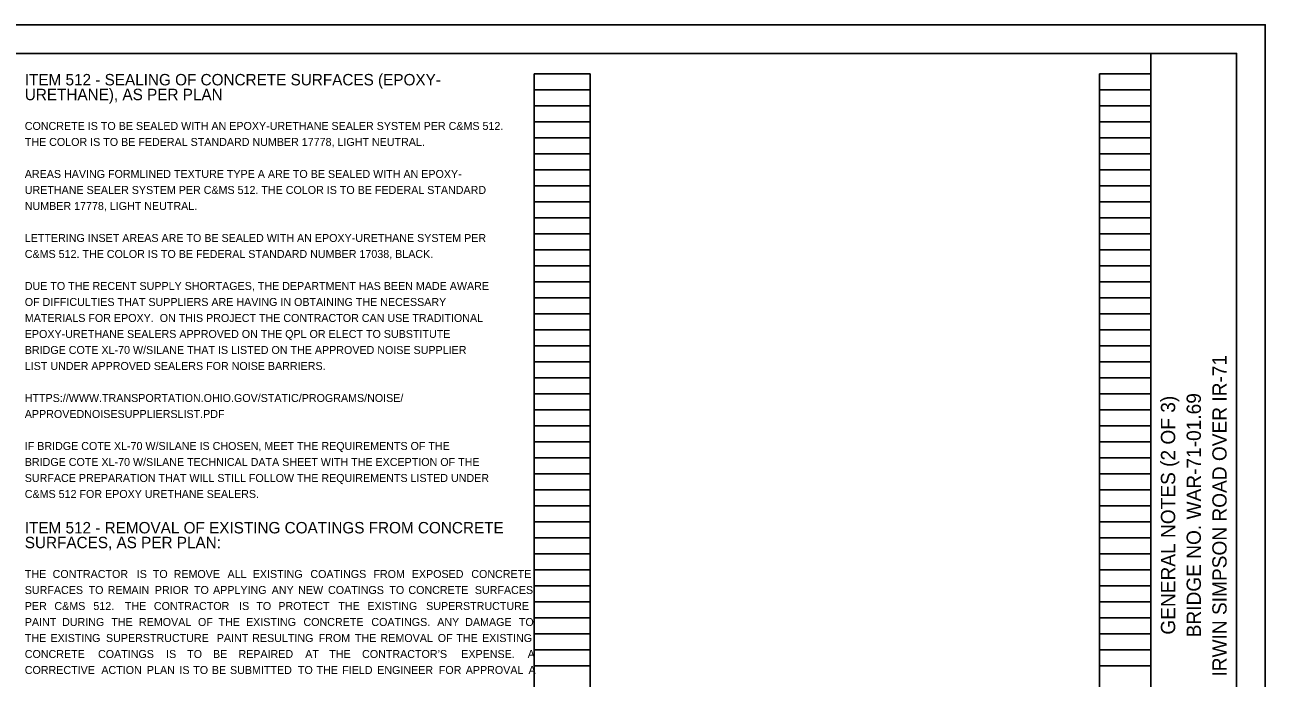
# Model space of a CAD drawing. Extents: x -20.1 to 34, y 0 to 22.
# Drawn here: x 12.29 to 34, y 10.57 to 22 of the extents above; entities that cross this region are included whole.
import ezdxf

# ---------------------------------------------------------------- set-up
doc = ezdxf.new("R2010")
doc.units = 0
for name, color, linetype in [('BR_P_Gen_Text', 7, 'Continuous'), ('SC_Scratch1', 7, 'Continuous'), ('SH_Border', 7, 'Continuous'), ('SH_Cut_Line', 7, 'Continuous'), ('SH_Data', 7, 'Continuous'), ('SH_Text', 7, 'Continuous')]:
    doc.layers.add(name, color=color, linetype=linetype)

msp = doc.modelspace()

# ---------------------------------------------------------------- linework, layer by layer
at = {"layer": 'SC_Scratch1'}
for p, q in [((21.207, 0.98), (21.207, 21.14)), ((21.207, 21.14), (22.187, 21.14)), ((22.187, 0.98), (22.187, 21.14)), ((31.1, 0.98), (31.1, 21.14)), ((31.1, 21.14), (32, 21.14)), ((32, 0.98), (32, 21.14)), ((21.207, 20.86), (22.187, 20.86)), ((31.1, 20.86), (32, 20.86)), ((21.207, 20.58), (22.187, 20.58)), ((31.1, 20.58), (32, 20.58)), ((21.207, 20.3), (22.187, 20.3)), ((31.1, 20.3), (32, 20.3)), ((21.207, 20.02), (22.187, 20.02)), ((31.1, 20.02), (32, 20.02)), ((21.207, 19.74), (22.187, 19.74)), ((31.1, 19.74), (32, 19.74)), ((21.207, 19.46), (22.187, 19.46)), ((31.1, 19.46), (32, 19.46)), ((21.207, 19.18), (22.187, 19.18)), ((31.1, 19.18), (32, 19.18)), ((21.207, 18.9), (22.187, 18.9)), ((31.1, 18.9), (32, 18.9)), ((21.207, 18.62), (22.187, 18.62)), ((31.1, 18.62), (32, 18.62)), ((21.207, 18.34), (22.187, 18.34)), ((31.1, 18.34), (32, 18.34)), ((21.207, 18.06), (22.187, 18.06)), ((31.1, 18.06), (32, 18.06)), ((21.207, 17.78), (22.187, 17.78)), ((31.1, 17.78), (32, 17.78)), ((21.207, 17.5), (22.187, 17.5)), ((31.1, 17.5), (32, 17.5)), ((21.207, 17.22), (22.187, 17.22)), ((31.1, 17.22), (32, 17.22)), ((21.207, 16.94), (22.187, 16.94)), ((31.1, 16.94), (32, 16.94)), ((21.207, 16.66), (22.187, 16.66)), ((31.1, 16.66), (32, 16.66)), ((21.207, 16.38), (22.187, 16.38)), ((31.1, 16.38), (32, 16.38)), ((21.207, 16.1), (22.187, 16.1)), ((31.1, 16.1), (32, 16.1)), ((21.207, 15.82), (22.187, 15.82)), ((31.1, 15.82), (32, 15.82)), ((21.207, 15.54), (22.187, 15.54)), ((31.1, 15.54), (32, 15.54)), ((21.207, 15.26), (22.187, 15.26)), ((31.1, 15.26), (32, 15.26)), ((21.207, 14.98), (22.187, 14.98)), ((31.1, 14.98), (32, 14.98)), ((21.207, 14.7), (22.187, 14.7)), ((31.1, 14.7), (32, 14.7)), ((21.207, 14.42), (22.187, 14.42)), ((31.1, 14.42), (32, 14.42)), ((21.207, 14.14), (22.187, 14.14)), ((31.1, 14.14), (32, 14.14)), ((21.207, 13.86), (22.187, 13.86)), ((31.1, 13.86), (32, 13.86)), ((21.207, 13.58), (22.187, 13.58)), ((31.1, 13.58), (32, 13.58)), ((21.207, 13.3), (22.187, 13.3)), ((31.1, 13.3), (32, 13.3)), ((21.207, 13.02), (22.187, 13.02)), ((31.1, 13.02), (32, 13.02)), ((21.207, 12.74), (22.187, 12.74)), ((31.1, 12.74), (32, 12.74)), ((21.207, 12.46), (22.187, 12.46)), ((31.1, 12.46), (32, 12.46)), ((21.207, 12.18), (22.187, 12.18)), ((31.1, 12.18), (32, 12.18)), ((21.207, 11.9), (22.187, 11.9)), ((31.1, 11.9), (32, 11.9)), ((21.207, 11.62), (22.187, 11.62)), ((31.1, 11.62), (32, 11.62)), ((21.207, 11.34), (22.187, 11.34)), ((31.1, 11.34), (32, 11.34)), ((21.207, 11.06), (22.187, 11.06)), ((31.1, 11.06), (32, 11.06)), ((21.207, 10.78), (22.187, 10.78)), ((31.1, 10.78), (32, 10.78))]:
    msp.add_line(p, q, dxfattribs=at)
msp.add_lwpolyline([(0, 22), (34, 22), (34, 0), (0, 0)], close=True, dxfattribs=at)
at = {"layer": 'SH_Border'}
msp.add_line((32, 0.5), (32, 21.5), dxfattribs=at)
msp.add_lwpolyline([(1.5, 21.5), (33.5, 21.5), (33.5, 0.5), (1.5, 0.5)], close=True, dxfattribs=at)
at = {"layer": 'SH_Cut_Line'}
msp.add_lwpolyline([(0, 0), (34, 0), (34, 22), (0, 22)], close=True, dxfattribs=at)

# ---------------------------------------------------------------- texts
at = {"layer": 'BR_P_Gen_Text'}
for s, p in [('ITEM 512 - SEALING OF CONCRETE SURFACES (EPOXY-', (12.293, 20.94)), ('URETHANE), AS PER PLAN', (12.293, 20.681)), ('ITEM 512 - REMOVAL OF EXISTING COATINGS FROM CONCRETE ', (12.293, 13.1)), ('SURFACES, AS PER PLAN:', (12.293, 12.841))]:
    msp.add_text(s, height=0.2, dxfattribs=at).set_placement(p)
at = {"layer": 'SH_Data'}
for s, p in [('IRWIN SIMPSON ROAD OVER IR-71', (33.325, 10.595)), ('GENERAL NOTES (2 OF 3)', (32.425, 11.329)), ('BRIDGE NO. WAR-71-01.69', (32.875, 11.282))]:
    msp.add_text(s, height=0.25, rotation=90, dxfattribs=at).set_placement(p)
at = {"layer": 'SH_Text'}
for s, p in [('CONCRETE IS TO BE SEALED WITH AN EPOXY-URETHANE SEALER SYSTEM PER C&MS 512. ', (12.293, 20.16)), ('THE COLOR IS TO BE FEDERAL STANDARD NUMBER 17778, LIGHT NEUTRAL. ', (12.293, 19.88)), ('AREAS HAVING FORMLINED TEXTURE TYPE A ARE TO BE SEALED WITH AN EPOXY-', (12.293, 19.32)), ('URETHANE SEALER SYSTEM PER C&MS 512. THE COLOR IS TO BE FEDERAL STANDARD ', (12.293, 19.04)), ('NUMBER 17778, LIGHT NEUTRAL. ', (12.293, 18.76)), ('LETTERING INSET AREAS ARE TO BE SEALED WITH AN EPOXY-URETHANE SYSTEM PER ', (12.293, 18.2)), ('C&MS 512. THE COLOR IS TO BE FEDERAL STANDARD NUMBER 17038, BLACK.', (12.293, 17.92)), ('DUE TO THE RECENT SUPPLY SHORTAGES, THE DEPARTMENT HAS BEEN MADE AWARE ', (12.293, 17.36)), ('OF DIFFICULTIES THAT SUPPLIERS ARE HAVING IN OBTAINING THE NECESSARY ', (12.293, 17.08)), ('MATERIALS FOR EPOXY.  ON THIS PROJECT THE CONTRACTOR CAN USE TRADITIONAL ', (12.293, 16.8)), ('EPOXY-URETHANE SEALERS APPROVED ON THE QPL OR ELECT TO SUBSTITUTE ', (12.293, 16.52)), ('BRIDGE COTE XL-70 W/SILANE THAT IS LISTED ON THE APPROVED NOISE SUPPLIER ', (12.293, 16.24)), ('LIST UNDER APPROVED SEALERS FOR NOISE BARRIERS.  ', (12.293, 15.96)), ('HTTPS://WWW.TRANSPORTATION.OHIO.GOV/STATIC/PROGRAMS/NOISE/', (12.293, 15.4)), ('APPROVEDNOISESUPPLIERSLIST.PDF ', (12.293, 15.12)), ('IF BRIDGE COTE XL-70 W/SILANE IS CHOSEN, MEET THE REQUIREMENTS OF THE ', (12.293, 14.56)), ('BRIDGE COTE XL-70 W/SILANE TECHNICAL DATA SHEET WITH THE EXCEPTION OF THE ', (12.293, 14.28)), ('SURFACE PREPARATION THAT WILL STILL FOLLOW THE REQUIREMENTS LISTED UNDER ', (12.293, 14)), ('C&MS 512 FOR EPOXY URETHANE SEALERS.', (12.293, 13.72)), ('THE ', (12.293, 12.32)), ('CONTRACTOR ', (12.78, 12.32)), ('IS ', (14.253, 12.32)), ('TO ', (14.534, 12.32)), ('REMOVE ', (14.898, 12.32)), ('ALL ', (15.841, 12.32)), ('EXISTING ', (16.282, 12.32)), ('COATINGS ', (17.291, 12.32)), ('FROM ', (18.394, 12.32)), ('EXPOSED ', (19.065, 12.32)), ('CONCRETE ', (20.107, 12.32)), ('SURFACES ', (12.293, 12.04)), ('TO ', (13.41, 12.04)), ('REMAIN ', (13.743, 12.04)), ('PRIOR ', (14.569, 12.04)), ('TO ', (15.254, 12.04)), ('APPLYING ', (15.588, 12.04)), ('ANY ', (16.614, 12.04)), ('NEW ', (17.078, 12.04)), ('COATINGS ', (17.6, 12.04)), ('TO ', (18.673, 12.04)), ('CONCRETE ', (19.006, 12.04)), ('SURFACES ', (20.169, 12.04)), ('PER ', (12.293, 11.76)), ('C&MS ', (12.812, 11.76)), ('512.  ', (13.493, 11.76)), ('THE ', (14.044, 11.76)), ('CONTRACTOR ', (14.552, 11.76)), ('IS ', (16.044, 11.76)), ('TO ', (16.345, 11.76)), ('PROTECT ', (16.73, 11.76)), ('THE ', (17.781, 11.76)), ('EXISTING ', (18.288, 11.76)), ('SUPERSTRUCTURE ', (19.317, 11.76)), ('PAINT ', (12.293, 11.48)), ('DURING ', (12.946, 11.48)), ('THE ', (13.808, 11.48)), ('REMOVAL ', (14.291, 11.48)), ('OF ', (15.324, 11.48)), ('THE ', (15.683, 11.48)), ('EXISTING ', (16.165, 11.48)), ('CONCRETE ', (17.17, 11.48)), ('COATINGS. ', (18.358, 11.48)), ('ANY ', (19.511, 11.48)), ('DAMAGE ', (20.001, 11.48)), ('TO ', (20.94, 11.48)), ('THE ', (12.293, 11.2)), ('EXISTING ', (12.743, 11.2)), ('SUPERSTRUCTURE ', (13.714, 11.2)), ('PAINT ', (15.653, 11.2)), ('RESULTING ', (16.273, 11.2)), ('FROM ', (17.436, 11.2)), ('THE ', (18.07, 11.2)), ('REMOVAL ', (18.519, 11.2)), ('OF ', (19.52, 11.2)), ('THE ', (19.846, 11.2)), ('EXISTING ', (20.296, 11.2)), ('CONCRETE ', (12.293, 10.92)), ('COATINGS ', (13.575, 10.92)), ('IS ', (14.766, 10.92)), ('TO ', (15.135, 10.92)), ('BE ', (15.587, 10.92)), ('REPAIRED ', (16.032, 10.92)), ('AT ', (17.201, 10.92)), ('THE ', (17.621, 10.92)), ('CONTRACTOR’S ', (18.196, 10.92)), ('EXPENSE. ', (19.931, 10.92)), ('A ', (21.093, 10.92)), ('CORRECTIVE ', (12.293, 10.64)), ('ACTION ', (13.633, 10.64)), ('PLAN ', (14.43, 10.64)), ('IS ', (14.999, 10.64)), ('TO ', (15.241, 10.64)), ('BE ', (15.567, 10.64)), ('SUBMITTED ', (15.885, 10.64)), ('TO ', (17.073, 10.64)), ('THE ', (17.399, 10.64)), ('FIELD ', (17.848, 10.64)), ('ENGINEER ', (18.46, 10.64)), ('FOR ', (19.539, 10.64)), ('APPROVAL ', (20.01, 10.64)), ('A ', (21.108, 10.64))]:
    msp.add_text(s, height=0.14, dxfattribs=at).set_placement(p)

doc.saveas('drawing.dxf')
